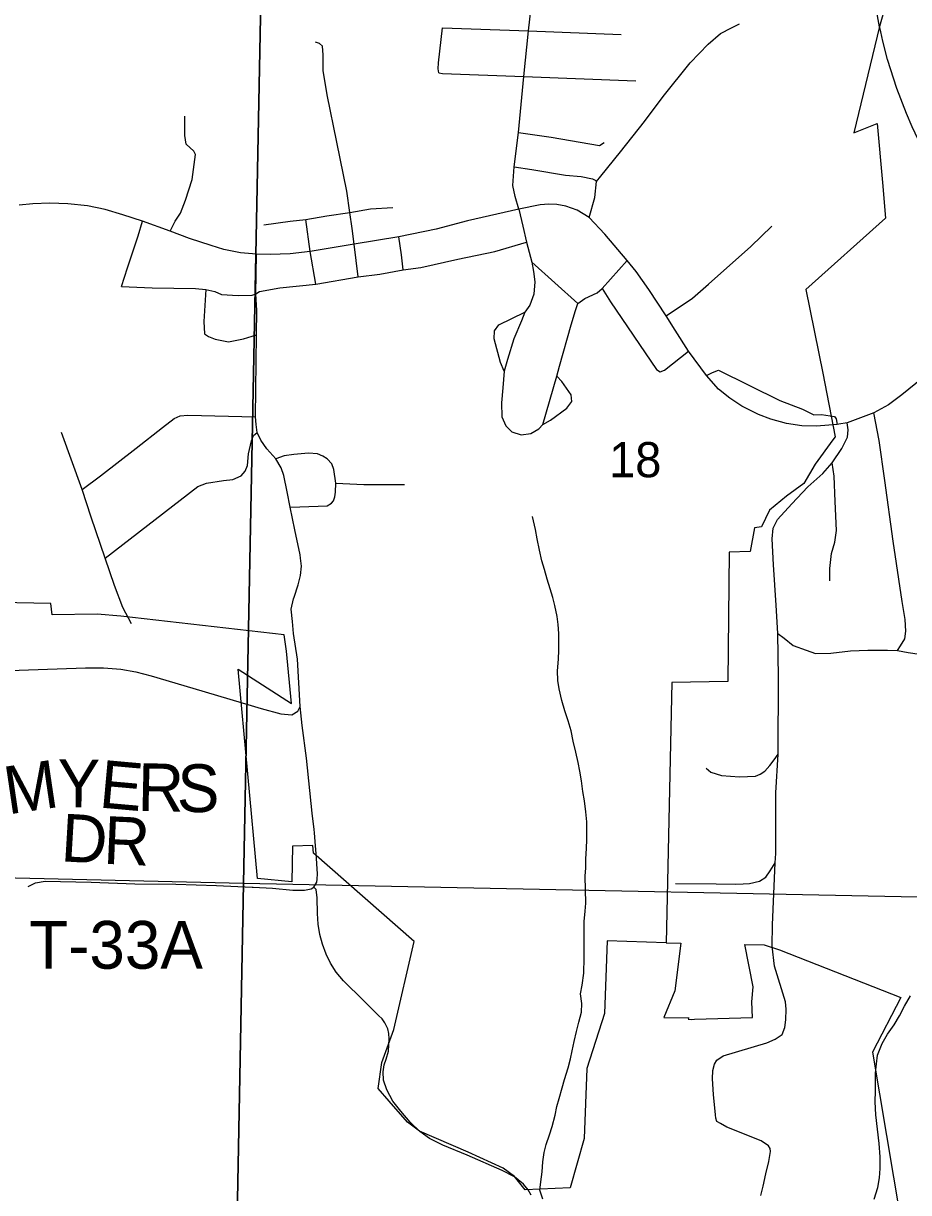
# Model space of a CAD drawing. Extents: x -19 to 40.8, y -1.8 to 26.1.
# Drawn here: x 7.005 to 8.058, y 14.485 to 15.876 of the extents above; entities that cross this region are included whole.
import ezdxf

# ---------------------------------------------------------------- set-up
doc = ezdxf.new("R2010")
doc.units = 0
for name, color, linetype in [('Default', 7, 'Continuous'), ('GM_X_City_Street', 7, 'Continuous'), ('GM_X_Corporation', 7, 'Continuous'), ('GM_X_Rail_Line', 7, 'Continuous'), ('GM_X_Rail_Line_Text', 7, 'Continuous'), ('GM_X_Section', 7, 'Continuous'), ('GM_X_Section_Text', 7, 'Continuous'), ('GM_X_State_Route', 7, 'Continuous'), ('GM_X_Township_Road_Text', 7, 'Continuous'), ('RW_P_Text', 7, 'Continuous')]:
    doc.layers.add(name, color=color, linetype=linetype)

msp = doc.modelspace()

# ---------------------------------------------------------------- linework, layer by layer
at = {"layer": 'Default'}
for p, q in [((8.0312, 15.8982), (8.0236, 15.8722)), ((8.0236, 15.8722), (7.9931, 15.7456)), ((7.9931, 15.7456), (8.0208, 15.7565)), ((8.0208, 15.7565), (8.0272, 15.6863)), ((8.0272, 15.6863), (8.0309, 15.6439)), ((8.0309, 15.6439), (7.936, 15.5591)), ((7.936, 15.5591), (7.9563, 15.4598)), ((7.9563, 15.4598), (7.971, 15.3841)), ((7.971, 15.3841), (7.9684, 15.3803)), ((7.9684, 15.3803), (7.9473, 15.3514)), ((7.9473, 15.3514), (7.9337, 15.3286)), ((7.9337, 15.3286), (7.9132, 15.3132)), ((7.9132, 15.3132), (7.893, 15.2967)), ((7.893, 15.2967), (7.8832, 15.2769)), ((7.8748, 15.2759), (7.8698, 15.2476)), ((7.8832, 15.2769), (7.8748, 15.2759)), ((7.8448, 15.2466), (7.8433, 15.0928)), ((7.8698, 15.2476), (7.8448, 15.2466)), ((7.7766, 15.0916), (7.7699, 14.7819)), ((7.8433, 15.0928), (7.7766, 15.0916)), ((7.7699, 14.7819), (7.7874, 14.7815)), ((7.7874, 14.7815), (7.78, 14.725)), ((7.8733, 14.7299), (7.8636, 14.7801)), ((7.8636, 14.7801), (7.8864, 14.7796)), ((7.8864, 14.7796), (7.9046, 14.7738)), ((7.9046, 14.7738), (8.0493, 14.717)), ((7.872, 14.7121), (7.8733, 14.7299)), ((7.78, 14.725), (7.7671, 14.6932)), ((8.0493, 14.717), (8.0153, 14.652)), ((7.8727, 14.6934), (7.872, 14.7121)), ((7.7671, 14.6932), (7.7969, 14.6927)), ((7.7969, 14.6927), (7.7961, 14.6911)), ((7.7961, 14.6911), (7.8005, 14.691)), ((7.8005, 14.691), (7.8035, 14.6911)), ((7.8035, 14.6911), (7.8727, 14.6934)), ((8.0153, 14.652), (8.0499, 14.4478))]:
    msp.add_line(p, q, dxfattribs=at)
for points in [[(6.2624, 14.1), (7.2527, 14.1), (7.2668, 14.8526), (6.2831, 14.8757)], [(7.2527, 14.1), (8.2764, 14.1), (8.2842, 14.8321), (7.2668, 14.8526)]]:
    msp.add_lwpolyline(points, close=True, dxfattribs=at)
at = {"layer": 'GM_X_City_Street'}
msp.add_lwpolyline([(8.0312, 15.8982), (8.0236, 15.8722), (7.9931, 15.7456), (8.0208, 15.7565), (8.0272, 15.6863), (8.0309, 15.6439), (7.936, 15.5591), (7.9563, 15.4598), (7.971, 15.3841), (7.9684, 15.3803), (7.9473, 15.3514), (7.9337, 15.3286), (7.9132, 15.3132), (7.893, 15.2967), (7.8832, 15.2769), (7.8748, 15.2759), (7.8698, 15.2476), (7.8448, 15.2466), (7.8433, 15.0928), (7.7766, 15.0916), (7.7699, 14.7819), (7.6997, 14.7844), (7.6966, 14.698), (7.6753, 14.6326), (7.6724, 14.5495), (7.6555, 14.4908), (7.602, 14.4881), (7.5892, 14.5041), (7.5759, 14.5142), (7.5341, 14.5329), (7.4764, 14.5582), (7.462, 14.5686), (7.4404, 14.5939), (7.4272, 14.6087), (7.4314, 14.6399), (7.4456, 14.6792), (7.47, 14.7837), (7.3502, 14.8889), (7.3494, 14.8978), (7.3251, 14.8972), (7.3242, 14.8548), (7.2837, 14.8586), (7.2605, 15.1078), (7.3238, 15.0666), (7.3181, 15.1289), (7.3152, 15.1486), (7.1208, 15.1707), (7.0927, 15.1731), (7.039, 15.1721), (7.0377, 15.1857), (6.8544, 15.1891)], dxfattribs=at)
at = {"layer": 'GM_X_Corporation'}
msp.add_line((7.3342, 15.0632), (7.3326, 15.0914), dxfattribs=at)
for points in [[(8.0252, 15.8656), (8.0238, 15.8716), (8.0193, 15.896), (8.0167, 15.9139), (8.0166, 15.9149)], [(8.1794, 15.5746), (8.1545, 15.6077), (8.1169, 15.6585), (8.0984, 15.6858), (8.0865, 15.706), (8.0729, 15.731), (8.0626, 15.7526), (8.0557, 15.7684), (8.0443, 15.7984), (8.0333, 15.8329), (8.0277, 15.8545), (8.0252, 15.8656)], [(7.3271, 15.1932), (7.332, 15.208), (7.3349, 15.2191), (7.336, 15.2301), (7.3348, 15.2397), (7.3344, 15.2437), (7.328, 15.2735), (7.3226, 15.3003), (7.319, 15.3185), (7.3147, 15.3378), (7.3118, 15.3469), (7.3052, 15.3577), (7.2946, 15.3696), (7.2875, 15.3801), (7.2833, 15.3893), (7.2819, 15.3987), (7.2813, 15.4077), (7.2823, 15.5054), (7.2826, 15.5342), (7.2816, 15.5539), (7.2824, 15.6014)], [(7.3326, 15.0914), (7.331, 15.1196), (7.3263, 15.1501), (7.325, 15.1644), (7.3237, 15.179), (7.3265, 15.1914), (7.3271, 15.1932)], [(6.977, 15.1057), (7.0789, 15.1092), (7.1004, 15.1092), (7.1208, 15.1077), (7.1388, 15.1044), (7.157, 15.0997), (7.2066, 15.0851), (7.2801, 15.0632)], [(7.2801, 15.0632), (7.2878, 15.0609), (7.3112, 15.0545), (7.3242, 15.0532), (7.3314, 15.0575), (7.3342, 15.0632)]]:
    msp.add_lwpolyline(points, dxfattribs=at)
at = {"layer": 'GM_X_Rail_Line'}
for points in [[(7.9755, 15.3989), (7.9735, 15.3986), (7.9488, 15.3967), (7.9315, 15.3972), (7.913, 15.3998), (7.8945, 15.4051), (7.8797, 15.4105), (7.86, 15.4204), (7.8456, 15.43), (7.832, 15.4407), (7.8178, 15.4571), (7.7966, 15.4857), (7.7804, 15.5109), (7.7698, 15.5278), (7.7493, 15.5592), (7.7341, 15.5805), (7.7234, 15.5937), (7.6968, 15.625), (7.6781, 15.645), (7.6639, 15.6535), (7.6503, 15.6584), (7.6398, 15.6604), (7.6303, 15.6608), (7.6198, 15.66), (7.5946, 15.6548), (7.5333, 15.6407), (7.4963, 15.631), (7.4516, 15.6219), (7.3987, 15.613), (7.3462, 15.6046), (7.3225, 15.6016), (7.2988, 15.6007), (7.2824, 15.6014), (7.2634, 15.6027), (7.2434, 15.6069), (7.2283, 15.6114), (7.2028, 15.62), (7.1796, 15.6285), (7.1465, 15.6405), (7.1232, 15.6482), (7.1024, 15.6542), (7.0811, 15.6587), (7.0578, 15.6613), (7.0365, 15.6621), (7.0162, 15.661), (6.9998, 15.6594)], [(8.1245, 15.49), (8.1178, 15.486), (8.1075, 15.4792), (8.0885, 15.4651), (8.0671, 15.4474), (8.0504, 15.434), (8.0343, 15.4221), (8.017, 15.4127), (7.9852, 15.4007), (7.9755, 15.3989)]]:
    msp.add_lwpolyline(points, dxfattribs=at)
at = {"layer": 'GM_X_Rail_Line_Text'}
msp.add_line((7.61, 15.5917), (7.6647, 15.5424), dxfattribs=at)
for points in [[(7.5946, 15.6548), (7.5902, 15.6697), (7.5874, 15.6829), (7.5891, 15.7052), (7.594, 15.7458), (7.6004, 15.8125), (7.6061, 15.8669), (7.6103, 15.9053), (7.6148, 15.947)], [(7.4992, 15.8171), (7.4987, 15.8216), (7.4991, 15.829), (7.5036, 15.8706)], [(7.5036, 15.8706), (7.6061, 15.8669), (7.7162, 15.8626)], [(7.6781, 15.645), (7.6848, 15.6687), (7.6871, 15.6876), (7.6922, 15.694), (7.7154, 15.723), (7.7439, 15.7589), (7.7662, 15.7889), (7.7985, 15.829), (7.8198, 15.851), (7.8344, 15.8636), (7.8477, 15.8706), (7.8571, 15.8754)], [(7.4034, 15.5743), (7.3987, 15.613), (7.3963, 15.6316), (7.3934, 15.6507), (7.3899, 15.676), (7.3778, 15.7345), (7.3665, 15.7906), (7.3615, 15.8197), (7.3615, 15.8385), (7.361, 15.8488), (7.3574, 15.852), (7.3525, 15.8533)], [(7.4992, 15.8171), (7.5035, 15.816), (7.6004, 15.8125), (7.7337, 15.8076)], [(7.1796, 15.6285), (7.1856, 15.6406), (7.192, 15.65), (7.198, 15.6654), (7.2057, 15.6901), (7.2096, 15.7196), (7.2076, 15.7239), (7.1988, 15.732), (7.1969, 15.7424), (7.197, 15.7652)], [(7.594, 15.7458), (7.6332, 15.7406), (7.6906, 15.7305), (7.696, 15.734)], [(7.5891, 15.7052), (7.6101, 15.7021), (7.65, 15.6954), (7.6689, 15.6935), (7.6821, 15.6908), (7.6854, 15.6893), (7.6871, 15.6876)], [(7.2911, 15.6361), (7.3223, 15.6403), (7.341, 15.6424), (7.3662, 15.6469), (7.3934, 15.6507), (7.4182, 15.655), (7.4444, 15.6567)], [(7.5946, 15.6548), (7.5991, 15.6344), (7.6036, 15.6155), (7.61, 15.5917), (7.6121, 15.5805), (7.6135, 15.5685), (7.6122, 15.5538), (7.6077, 15.5405), (7.6015, 15.5323), (7.5978, 15.5218), (7.5887, 15.5005), (7.5812, 15.476), (7.5771, 15.462), (7.5753, 15.4423), (7.574, 15.4246), (7.5744, 15.4077), (7.579, 15.397), (7.5862, 15.3898), (7.5972, 15.3864), (7.6087, 15.3879), (7.6183, 15.3934), (7.6231, 15.3986), (7.6397, 15.4562), (7.6428, 15.4679), (7.6568, 15.5173), (7.6621, 15.5344), (7.6647, 15.5424), (7.6732, 15.5485), (7.6877, 15.5551), (7.6937, 15.5603), (7.7234, 15.5937)], [(7.1218, 15.5626), (7.1289, 15.585), (7.1417, 15.6232), (7.1465, 15.6405)], [(7.353, 15.5654), (7.3462, 15.6046), (7.341, 15.6424)], [(7.7698, 15.5278), (7.8013, 15.5491), (7.8201, 15.5655), (7.8708, 15.6103), (7.8957, 15.6344)], [(7.4567, 15.5828), (7.4548, 15.6005), (7.4516, 15.6219)], [(7.2816, 15.5539), (7.2859, 15.557), (7.31, 15.5611), (7.353, 15.5654), (7.4034, 15.5743), (7.4293, 15.5774), (7.4567, 15.5828), (7.478, 15.5854), (7.5221, 15.5951), (7.5658, 15.6046), (7.6036, 15.6155)], [(7.1218, 15.5626), (7.158, 15.5611), (7.2096, 15.5604), (7.2219, 15.5592), (7.2326, 15.557), (7.2406, 15.5533), (7.2605, 15.552), (7.2773, 15.5524), (7.2816, 15.5539)], [(7.2219, 15.5592), (7.2197, 15.521), (7.2205, 15.5066), (7.2253, 15.5033), (7.2332, 15.5001), (7.2491, 15.4971), (7.2669, 15.5004), (7.2823, 15.5054)], [(7.6937, 15.5603), (7.7038, 15.5446), (7.7583, 15.4639), (7.7628, 15.4612), (7.7678, 15.4633), (7.7966, 15.4857)], [(7.5771, 15.462), (7.5726, 15.4725), (7.5651, 15.5006), (7.5657, 15.5102), (7.5707, 15.517), (7.6015, 15.5323)], [(7.6231, 15.3986), (7.6324, 15.4038), (7.6518, 15.418), (7.6576, 15.4261), (7.6569, 15.4338), (7.6456, 15.4498), (7.6397, 15.4562)], [(7.8178, 15.4571), (7.825, 15.4606), (7.8322, 15.4632), (7.9052, 15.427), (7.932, 15.4168), (7.9456, 15.4102), (7.9548, 15.4105), (7.9652, 15.409), (7.9701, 15.408), (7.9723, 15.4052), (7.9735, 15.3986)], [(7.075, 15.3215), (7.0967, 15.3374), (7.1393, 15.3705), (7.1704, 15.395), (7.1842, 15.4057), (7.1916, 15.409), (7.2005, 15.4098), (7.2813, 15.4077)], [(8.0453, 15.1298), (8.0489, 15.1354), (8.0537, 15.1436), (8.0549, 15.1529), (8.0542, 15.1668), (8.0508, 15.1879), (8.0399, 15.2599), (8.0299, 15.3322), (8.0234, 15.3798), (8.017, 15.4127)], [(7.896, 14.778), (7.8965, 14.8035), (7.8996, 14.8773), (7.9005, 14.8883), (7.9005, 14.9164), (7.9002, 14.9607), (7.9032, 15.0067), (7.9034, 15.0981), (7.9028, 15.1502), (7.9007, 15.1838), (7.8974, 15.2316), (7.896, 15.2625), (7.897, 15.2752), (7.9023, 15.2858), (7.9194, 15.3041), (7.9383, 15.3244), (7.9562, 15.3404), (7.9676, 15.3529), (7.9789, 15.3699), (7.9856, 15.3834), (7.9864, 15.3922), (7.9852, 15.4007)], [(7.1335, 15.1614), (7.1232, 15.1811), (7.1133, 15.2073), (7.1021, 15.2396), (7.0857, 15.2885), (7.075, 15.3215), (7.0503, 15.3893)], [(7.1021, 15.2396), (7.2125, 15.3249), (7.2228, 15.329), (7.2429, 15.332), (7.2543, 15.3334), (7.2639, 15.3375), (7.2689, 15.343), (7.2715, 15.3499), (7.273, 15.3638), (7.2762, 15.3793), (7.2788, 15.3857), (7.2833, 15.3893)], [(7.3226, 15.3003), (7.3339, 15.3007), (7.3666, 15.3019), (7.3716, 15.3049), (7.374, 15.308), (7.3755, 15.3127), (7.3762, 15.3182), (7.3767, 15.3289), (7.3744, 15.345), (7.3721, 15.3517), (7.3664, 15.3579), (7.3614, 15.361), (7.3551, 15.3636), (7.3442, 15.3647), (7.3269, 15.363), (7.3152, 15.3612), (7.3052, 15.3577)], [(7.9647, 15.2125), (7.9648, 15.2272), (7.9666, 15.2452), (7.9706, 15.2587), (7.9724, 15.2727), (7.971, 15.3072), (7.9699, 15.3372), (7.9676, 15.3529)], [(7.3767, 15.3289), (7.4102, 15.3273), (7.4585, 15.3271)], [(7.9028, 15.1502), (7.9102, 15.1444), (7.921, 15.1357), (7.9363, 15.1302), (7.9476, 15.1262), (7.966, 15.1266), (7.9894, 15.1293), (8.0099, 15.1304), (8.0333, 15.1304), (8.0453, 15.1298), (8.0579, 15.1274), (8.0715, 15.1254)], [(7.8175, 14.9899), (7.8232, 14.9852), (7.8356, 14.981), (7.857, 14.9794), (7.876, 14.9802), (7.8819, 14.9827), (7.8871, 14.9861), (7.8934, 14.9929), (7.8984, 14.9999), (7.9032, 15.0067)], [(7.7809, 14.8525), (7.8292, 14.8521), (7.8522, 14.852), (7.8615, 14.8522), (7.8691, 14.8528), (7.881, 14.8555), (7.8885, 14.8603), (7.8938, 14.8677), (7.8996, 14.8773)]]:
    msp.add_lwpolyline(points, dxfattribs=at)
at = {"layer": 'GM_X_Section'}
for points in [[(7.6229, 14.4773), (7.6196, 14.4879), (7.6206, 14.4978), (7.6222, 14.5096), (7.6231, 14.5214), (7.6248, 14.5328), (7.6272, 14.5424), (7.6312, 14.5539), (7.634, 14.5638), (7.6376, 14.5772), (7.6396, 14.5875), (7.6425, 14.5971), (7.646, 14.6097), (7.6488, 14.6196), (7.6531, 14.6334), (7.6559, 14.6441), (7.658, 14.6536), (7.6605, 14.6647), (7.6633, 14.6765), (7.6661, 14.6876), (7.6692, 14.6998), (7.6694, 14.7101), (7.668, 14.7215), (7.6697, 14.7318), (7.6717, 14.7459), (7.6721, 14.7641), (7.6723, 14.774), (7.6724, 14.7862), (7.6722, 14.7968), (7.6724, 14.8075), (7.6733, 14.8197), (7.6742, 14.8292), (7.6735, 14.8615), (7.6741, 14.8714), (7.6743, 14.882), (7.6752, 14.8942), (7.6753, 14.9049), (7.6755, 14.9167), (7.6756, 14.9262), (7.6743, 14.9379), (7.6725, 14.9508), (7.6707, 14.9622), (7.669, 14.9747), (7.6672, 14.9861), (7.6651, 14.9967), (7.6622, 15.0088), (7.6593, 15.022), (7.6567, 15.0342), (7.6534, 15.0463), (7.6494, 15.058), (7.6457, 15.0704), (7.6424, 15.0841), (7.6411, 15.0943), (7.6405, 15.1057), (7.6417, 15.1194), (7.6422, 15.1301), (7.642, 15.1396), (7.6422, 15.1502), (7.6412, 15.1608), (7.6403, 15.1703), (7.6374, 15.1832), (7.6349, 15.193), (7.632, 15.2032), (7.6284, 15.2146), (7.6251, 15.2263), (7.6218, 15.2365), (7.6193, 15.249), (7.6164, 15.2626), (7.6142, 15.2736), (7.6121, 15.2842), (7.6109, 15.2891)], [(8.0172, 14.4773), (8.0219, 14.4911), (8.0236, 14.5025), (8.0245, 14.5135), (8.0246, 14.5276), (8.0235, 14.5436), (8.0194, 14.5777), (8.0187, 14.5929), (8.0188, 14.6062), (8.019, 14.6161), (8.0191, 14.6271), (8.02, 14.6382), (8.0213, 14.6485), (8.0268, 14.6622), (8.0334, 14.6734), (8.0411, 14.6846), (8.0474, 14.6953), (8.0536, 14.7069), (8.0605, 14.7192)]]:
    msp.add_lwpolyline(points, dxfattribs=at)
at = {"layer": 'GM_X_State_Route'}
msp.add_line((7.3508, 14.9168), (7.3487, 14.9363), dxfattribs=at)
for points in [[(7.3487, 14.9363), (7.3419, 15.0016), (7.3367, 15.0408), (7.3342, 15.0632)], [(7.3525, 14.8973), (7.3512, 14.9129), (7.3508, 14.9168)], [(7.3544, 14.8578), (7.3551, 14.8643), (7.3532, 14.8885), (7.3525, 14.8973)], [(7.0105, 14.8492), (7.0195, 14.8536), (7.0308, 14.8554), (7.0856, 14.8544), (7.1374, 14.8524), (7.1863, 14.8519), (7.2349, 14.8504), (7.2773, 14.8485), (7.2785, 14.8484)], [(7.4365, 14.6436), (7.4394, 14.6532), (7.4404, 14.6681), (7.44, 14.6741), (7.4388, 14.6797), (7.4352, 14.6868), (7.4317, 14.6915), (7.4276, 14.6957), (7.4097, 14.7134), (7.3859, 14.7368), (7.3773, 14.7471), (7.3703, 14.758), (7.3653, 14.7687), (7.3607, 14.7804), (7.3578, 14.792), (7.3559, 14.8042), (7.3551, 14.8171), (7.3546, 14.8356), (7.3533, 14.8454), (7.3506, 14.8482), (7.354, 14.8542), (7.3544, 14.8578)], [(7.2785, 14.8484), (7.3013, 14.847), (7.3257, 14.8448), (7.327, 14.8448)], [(7.327, 14.8448), (7.3395, 14.8448), (7.3473, 14.8463), (7.3506, 14.8482)], [(7.8827, 14.4814), (7.8854, 14.4928), (7.8885, 14.5072), (7.892, 14.5218), (7.8941, 14.5337), (7.8938, 14.5376), (7.8917, 14.5407), (7.8831, 14.5464), (7.8421, 14.5628), (7.8345, 14.567), (7.8302, 14.5696), (7.8289, 14.5735), (7.8287, 14.5775), (7.8261, 14.6018), (7.8249, 14.6202), (7.8254, 14.6303), (7.8274, 14.6379), (7.8303, 14.6427), (7.8376, 14.6475), (7.8896, 14.6632), (7.8995, 14.6674), (7.9078, 14.673), (7.9111, 14.6815), (7.9123, 14.6906), (7.9128, 14.7031), (7.9117, 14.7121), (7.8986, 14.7544), (7.896, 14.778)], [(7.6092, 14.4819), (7.6055, 14.4883), (7.6002, 14.4951), (7.5894, 14.5036), (7.5747, 14.5113), (7.5332, 14.5297), (7.504, 14.5416), (7.4883, 14.5493), (7.4766, 14.5577), (7.4654, 14.5688), (7.454, 14.5819), (7.4447, 14.5939), (7.4374, 14.6072), (7.4334, 14.6187), (7.433, 14.6286), (7.4344, 14.6369), (7.4365, 14.6436)]]:
    msp.add_lwpolyline(points, dxfattribs=at)
at = {"layer": 'RW_P_Text'}
for points in [[(6.2953, 15.9429), (7.2877, 15.9238), (7.2668, 14.8526), (6.2831, 14.8757)], [(7.2877, 15.9238), (8.2983, 15.9055), (8.2842, 14.8321), (7.2668, 14.8526)]]:
    msp.add_lwpolyline(points, close=True, dxfattribs=at)

# ---------------------------------------------------------------- texts
at = {"layer": 'GM_X_Section_Text'}
msp.add_text('18', height=0.04186, rotation=0, dxfattribs=at).set_placement((7.7019, 15.3359))
at = {"layer": 'GM_X_Township_Road_Text'}
for s, height, rotation, p in [('M', 0.0568, 8.4304, (6.9865, 14.9347)), ('Y', 0.0568, 359.4609, (7.0452, 14.9436)), ('E', 0.0568, 354.8719, (7.0939, 14.9432)), ('R', 0.0568, 358.7859, (7.1405, 14.9391)), ('S', 0.0568, 358.949, (7.1873, 14.9381)), ('D', 0.0568, 356.6395, (7.0486, 14.8792)), ('R', 0.0568, 357.4514, (7.0994, 14.8762)), ('T-33A', 0.05682, 0.002, (7.0117, 14.7513))]:
    msp.add_text(s, height=height, rotation=rotation, dxfattribs=at).set_placement(p)

doc.saveas('drawing.dxf')
